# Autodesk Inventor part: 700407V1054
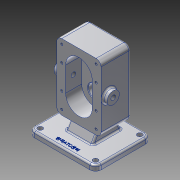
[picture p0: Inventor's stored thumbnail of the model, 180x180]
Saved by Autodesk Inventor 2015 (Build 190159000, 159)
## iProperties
Created: 2020-04
Part Number: 700407V1054
Material: 알루미늄 6061
Document SubType Name: Modeling
Designer: 1019876
Density: 2.7 g/cm^3
Appearance: 알루미늄 - 평지
Mass: 1470.94 g
Surface Area: 817.421 cm^2
Volume: 544.793 cm^3
Author: 1019876
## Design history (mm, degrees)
sketch "스케치1"
  geometry: L1 (60, -50)-(-60, -50); L2 (-60, -50)-(-60, 50); L3 (-60, 50)-(60, 50); L4 (60, 50)-(60, -50); L5 (60, -50)-(-60, 50); L6 (-60, -50)-(60, 50); 1 further point
  constraints: 12 end point, 2 midpoint, 2 parallel, 1 horizontal, 1 perpendicular
  dimensions: "d0" = 120 distance of L2.end L3.end; "d1" = 100 distance of L1.end L2.end
extrude "돌출1" new body sketch "스케치1" distance "d2" = 10; taper "d3" = 0 deg
sketch "스케치2"
  geometry: L1 (60, 50)-(-60, 50) reference; L2 (-24, -20)-(24, -20); L3 (24, -20)-(24, 33); L4 (24, 33)-(-24, 33); L5 (-24, 33)-(-24, -20); 1 further point
  constraints: 8 end point, 2 parallel, 1 horizontal, 1 perpendicular
  dimensions: "d4" = 17 distance between parallel lines of L1 L4; "d5" = 53 distance of L4.end L2.start; "d6" = 48 distance of L3.end L4.end; "d7" = 24 distance from line of L5 point (0, 0)
extrude "돌출2" join sketch "스케치2" distance "d8" = 70; taper "d9" = 0 deg
feature "면 기울기1" dims angle "d10" = 30 deg
node "작업 평면1"
sketch "스케치3"
  geometry: L1 (120, 0)-(120, -10) reference; L2 (120, -10)-(84, -10) reference; L3 (84, -10)-(36, -10) reference; L4 (36, -10)-(0, -10) reference; L5 (0, -10)-(0, 0) reference; L6 (0, 0)-(120, 0) reference; L7 (100, -150)-(20, -150); L8 (20, -150)-(20, -30); L9 (20, -30)-(100, -30); L10 (100, -30)-(100, -150); 1 further point
  constraints: 8 end point, 2 parallel, 1 horizontal, 1 perpendicular
  dimensions: "d12" = 150 distance between parallel lines of L6 L7; "d13" = 120 distance between parallel lines of L9 L7; "d14" = 80 distance of L7.start L7.end; "d15" = 40 distance from line of point (60, 0) L10
extrude "돌출3" join sketch "스케치3" distance "d16" = 53; taper "d17" = 0 deg
sketch "스케치4"
  geometry: L1 (100, 150)-(20, 150) reference; L2 (60, 44)-(60, 136); L3 (84, 68)-(84, 112); L4 (36, 112)-(36, 68); L5 (20, 150)-(20, 30) reference; A1 r 24 centre (60, 68) between (36, 68) and (84, 68); A2 r 24 centre (60, 112) between (84, 112) and (36, 112); 2 further points
  constraints: 8 end point, 6 point on circle, 4 tangent, 2 centre point, 2 point on line, 1 midpoint, 1 parallel, 1 vertical
  dimensions: "d18" = 92 distance of L2.start L2.end; "d19" = 24 radius of A2; "d20" = 60 distance from line of L1 point (60, 90); "d23" = 40 distance from line of L5 point (60, 90)
extrude "돌출4" cut sketch "스케치4" distance "d21" = 29; taper "d22" = 0 deg
sketch "스케치5"
  geometry: A1 r 24 centre (60, 112) between (84, 112) and (36, 112) reference; 1 further point
hole "구멍1" sketch "스케치5" at (60, 112) diameter "d24" = 17; stored, may be unused: countersink angle "d28" = 90 deg, drill point angle "d30" = 118 deg; dims "d25" = 6, "d26" = 25, "d27" = 15, "d29" = 8
sketch "스케치7"
  geometry: C1 r 8.5 at (60, -112) reference; C2 r 19 at (60, -112); 1 further point
  constraints: 1 centre point, 1 coincident
  dimensions: "d38" = 38 diameter of C2
extrude "돌출5" join sketch "스케치7" distance "d39" = 17; taper "d40" = 0 deg
sketch "스케치8"
  geometry: C1 r 8.5 at (0, 0) reference; 1 further point
hole "구멍3" sketch "스케치8" at (0, 0) diameter "d41" = 28; stored, may be unused: countersink angle "d45" = 90 deg, drill point angle "d47" = 118 deg; dims "d42" = 6, "d43" = 25, "d44" = 15, "d46" = 7.3
sketch "스케치9"
  geometry: C1 r 12.5 at (60, 68); A1 r 24 centre (60, 68) between (36, 68) and (84, 68) reference; 1 further point
  constraints: 1 centre point, 1 coincident
  dimensions: "d48" = 25 diameter of C1
extrude "돌출6" cut sketch "스케치9" distance "d49" = 15; taper "d50" = 0 deg
node "작업 평면2"
sketch "스케치10"
  geometry: L1 (150, 17)-(150, -83) reference; L2 (120, -53)-(0, -53) reference; C1 r 11 at (60, -39); 1 further point
  constraints: 1 centre point
  dimensions: "d52" = 90 distance from line of L1 C1.centre; "d53" = 14 distance from line of L2 C1.centre; "d54" = 22 diameter of C1
extrude "돌출7" join sketch "스케치10" stored distance "d55" = 15; taper "d56" = 0 deg
sketch "스케치11"
  geometry: C1 r 11 at (0, 0) reference; 1 further point
hole "구멍4" sketch "스케치11" at (0, 0) diameter "d57" = 8.376; stored, may be unused: countersink angle "d61" = 90 deg, drill point angle "d63" = 118 deg; dims "d58" = 26, "d59" = 25, "d60" = 15, "d62" = 33.3
fillet "모깎기1" dims "d64" = 9
sketch "스케치12"
  geometry: A1 r 9 centre (29, 39) between (20, 39) and (29, 30) reference; A2 r 9 centre (29, 141) between (29, 150) and (20, 141) reference; 3 further points
  constraints: 2 vertical alignment
  dimensions: "d65" = 29 distance of A2.centre point (29, 112); "d66" = 73 distance of point (29, 68) A2.centre
hole "구멍5" sketch "스케치12" at (29, 112), (29, 68), (29, 141), (29, 39) diameter "d67" = 4.134; stored, may be unused: countersink angle "d71" = 90 deg, drill point angle "d73" = 118 deg; dims "d68" = 10, "d69" = 25, "d70" = 15, "d72" = 12
fillet "모깎기2" dims "d74" = 10
sketch "스케치13"
  geometry: A1 r 10 centre (-50, 40) between (-50, 50) and (-60, 40) reference; A2 r 10 centre (-50, -40) between (-60, -40) and (-50, -50) reference; A3 r 10 centre (50, -40) between (50, -50) and (60, -40) reference; A4 r 10 centre (50, 40) between (60, 40) and (50, 50) reference; 1 further point
hole "구멍6" sketch "스케치13" at (50, 40), (-50, 40), (50, -40), (-50, -40) diameter "d75" = 9; stored, may be unused: countersink angle "d79" = 90 deg, drill point angle "d81" = 118 deg; dims "d76" = 10, "d77" = 25, "d78" = 15, "d80" = 12
sketch "스케치14"
  geometry: L1 (-60, 40)-(-60, -40) reference; L2 (-50, -50)-(50, -50) reference; 2 further points
  constraints: 1 other
  dimensions: "d82" = 60 distance from line of L1 point (0, -40); "d83" = 10 distance from line of L2 point (0, -40)
feature "엠보싱1" sketch "스케치14" dims "d0" = 120, "d1" = 100, "d84" = 0.5, "d85" = 0
chamfer "모따기1" distance "d86" = 0.7; stored, may be unused: second distance "d87" = 2, angle "d88" = 30 deg
fillet "모깎기3" dims "d89" = 0.5
chamfer "모따기2" distance "d90" = 1; stored, may be unused: second distance "d91" = 2, angle "d92" = 30 deg
fillet "모깎기4" dims "d93" = 3
fillet "모깎기5" dims "d94" = 3
fillet "모깎기6" dims "d95" = 3
fillet "모깎기7" dims "d96" = 3
node "솔리드1"
mirror "대칭1"
mirror "대칭2"
node "절단 모서리 투영1"
other parameters: "d11" = -17, "d51" = 8
